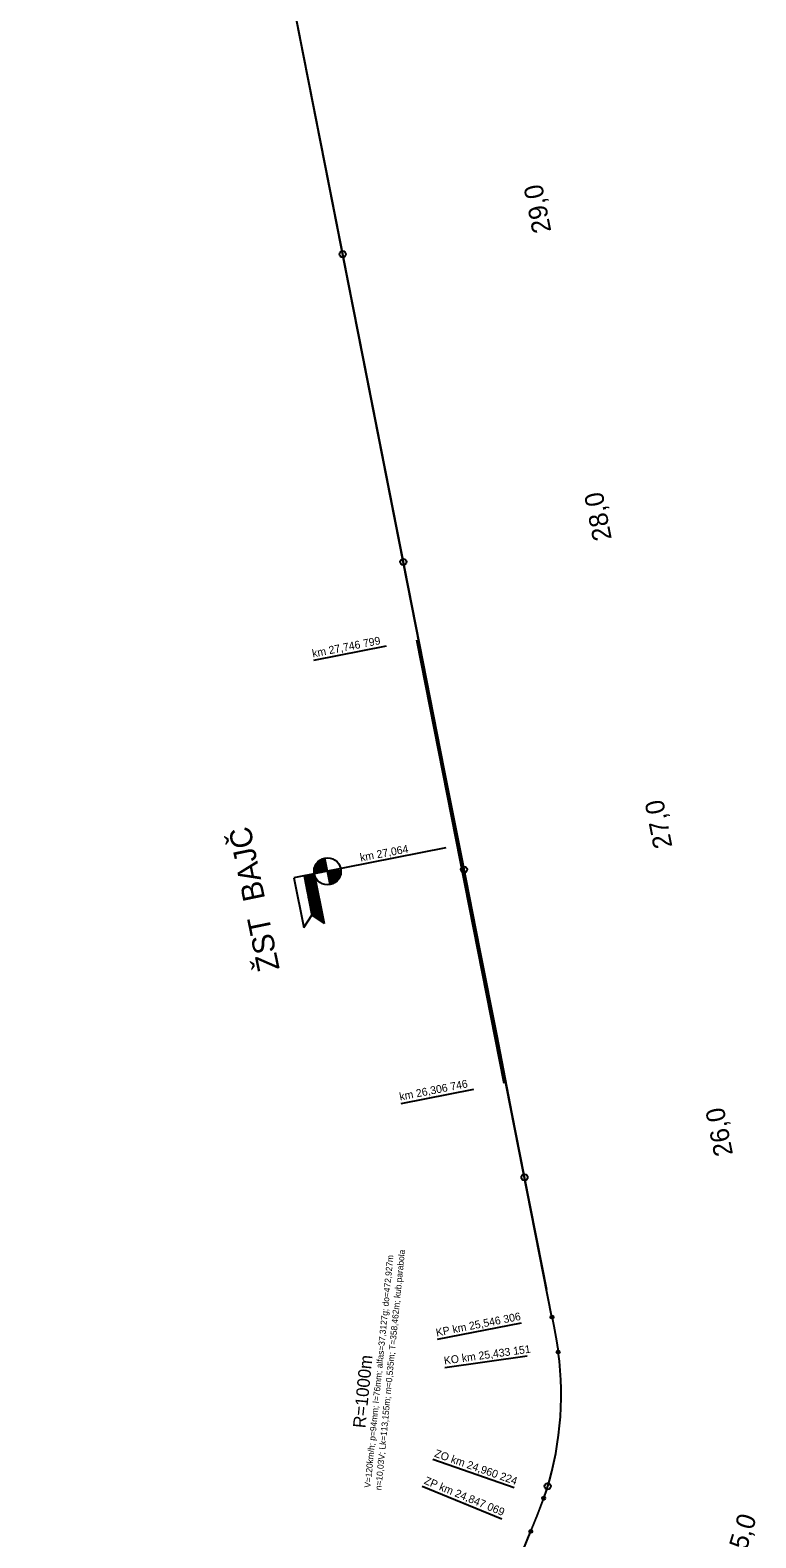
# Model space of a CAD drawing. Extents: x -504999 to -493096, y -1330712 to -1305226.
# Drawn here: x -495411 to -493096, y -1314840 to -1310033 of the extents above; entities that cross this region are included whole.
import ezdxf

# ---------------------------------------------------------------- set-up
doc = ezdxf.new("R2010")
doc.units = 0
for name, color, linetype in [('0_HM', 7, 'Continuous'), ('0_obluky', 7, 'Continuous'), ('0_popis oblukov', 7, 'Continuous'), ('0_STANICE', 7, 'Continuous'), ('0_stanicenie oblukov', 7, 'Continuous'), ('dotyčnice', 7, 'Continuous'), ('Level 1', 7, 'Continuous'), ('PHS', 7, 'Continuous')]:
    doc.layers.add(name, color=color, linetype=linetype)

msp = doc.modelspace()

# ---------------------------------------------------------------- linework, layer by layer
at = {"layer": '0_HM'}
for centre in [(-494413.4, -1310746.9), (-494220.1, -1311728), (-494026.8, -1312709.2), (-493833.6, -1313690.3), (-493759.9, -1314675.3)]:
    msp.add_circle(centre, 10, dxfattribs=at)
at = {"layer": '0_obluky'}
for p, q in [((-493745.9, -1314135.5), (-495397.2, -1305753.2)), ((-494814.6, -1317243.2), (-493813.4, -1314818.5))]:
    msp.add_line(p, q, dxfattribs=at)
for points in [[(-493745.9, -1314135.5), (-493745.7, -1314136.4), (-493745.5, -1314137.4), (-493745.3, -1314138.4), (-493745.1, -1314139.4), (-493744.9, -1314140.4), (-493744.7, -1314141.4), (-493744.5, -1314142.3), (-493744.3, -1314143.3), (-493744.1, -1314144.3), (-493743.9, -1314145.3), (-493743.7, -1314146.3), (-493743.5, -1314147.2), (-493743.4, -1314148.2), (-493743.2, -1314149.2), (-493743, -1314150.2), (-493742.8, -1314151.2), (-493742.6, -1314152.2), (-493742.4, -1314153.1), (-493742.2, -1314154.1), (-493742, -1314155.1), (-493741.8, -1314156.1), (-493741.6, -1314157.1), (-493741.4, -1314158.1), (-493741.2, -1314159), (-493741, -1314160), (-493740.9, -1314161), (-493740.7, -1314162), (-493740.5, -1314163), (-493740.3, -1314164), (-493740.1, -1314164.9), (-493739.9, -1314165.9), (-493739.7, -1314166.9), (-493739.5, -1314167.9), (-493739.3, -1314168.9), (-493739.2, -1314169.8), (-493739, -1314170.8), (-493738.8, -1314171.8), (-493738.6, -1314172.8), (-493738.4, -1314173.8), (-493738.2, -1314174.8), (-493738, -1314175.7), (-493737.8, -1314176.7), (-493737.7, -1314177.7), (-493737.5, -1314178.7), (-493737.3, -1314179.7), (-493737.1, -1314180.7), (-493736.9, -1314181.7), (-493736.7, -1314182.6), (-493736.6, -1314183.6), (-493736.4, -1314184.6), (-493736.2, -1314185.6), (-493736, -1314186.6), (-493735.8, -1314187.6), (-493735.6, -1314188.5), (-493735.5, -1314189.5), (-493735.3, -1314190.5), (-493735.1, -1314191.5), (-493734.9, -1314192.5), (-493734.7, -1314193.5), (-493734.6, -1314194.5), (-493734.4, -1314195.4), (-493734.2, -1314196.4), (-493734, -1314197.4), (-493733.9, -1314198.4), (-493733.7, -1314199.4), (-493733.5, -1314200.4), (-493733.3, -1314201.4), (-493733.2, -1314202.3), (-493733, -1314203.3), (-493732.8, -1314204.3), (-493732.6, -1314205.3), (-493732.5, -1314206.3), (-493732.3, -1314207.3), (-493732.1, -1314208.3), (-493732, -1314209.2), (-493731.8, -1314210.2), (-493731.6, -1314211.2), (-493731.5, -1314212.2), (-493731.3, -1314213.2), (-493731.1, -1314214.2), (-493731, -1314215.2), (-493730.8, -1314216.2), (-493730.6, -1314217.1), (-493730.5, -1314218.1), (-493730.3, -1314219.1), (-493730.1, -1314220.1), (-493730, -1314221.1), (-493729.8, -1314222.1), (-493729.7, -1314223.1), (-493729.5, -1314224.1), (-493729.3, -1314225.1), (-493729.2, -1314226), (-493729, -1314227), (-493728.9, -1314228), (-493728.7, -1314229), (-493728.6, -1314230), (-493728.4, -1314231), (-493728.3, -1314232), (-493728.1, -1314233), (-493728, -1314234), (-493727.8, -1314235), (-493727.7, -1314235.9), (-493727.5, -1314236.9), (-493727.4, -1314237.9), (-493727.2, -1314238.9), (-493727.1, -1314239.9), (-493726.9, -1314240.9), (-493726.8, -1314241.9), (-493726.7, -1314242.9), (-493726.5, -1314243.9), (-493726.4, -1314244.9), (-493726.2, -1314245.9), (-493726.1, -1314246.9)], [(-493813.4, -1314818.5), (-493813, -1314817.6), (-493812.6, -1314816.6), (-493812.2, -1314815.7), (-493811.9, -1314814.8), (-493811.5, -1314813.9), (-493811.1, -1314812.9), (-493810.7, -1314812), (-493810.3, -1314811.1), (-493809.9, -1314810.2), (-493809.6, -1314809.2), (-493809.2, -1314808.3), (-493808.8, -1314807.4), (-493808.4, -1314806.5), (-493808, -1314805.5), (-493807.7, -1314804.6), (-493807.3, -1314803.7), (-493806.9, -1314802.8), (-493806.5, -1314801.8), (-493806.1, -1314800.9), (-493805.8, -1314800), (-493805.4, -1314799.1), (-493805, -1314798.1), (-493804.6, -1314797.2), (-493804.2, -1314796.3), (-493803.9, -1314795.3), (-493803.5, -1314794.4), (-493803.1, -1314793.5), (-493802.7, -1314792.6), (-493802.3, -1314791.6), (-493802, -1314790.7), (-493801.6, -1314789.8), (-493801.2, -1314788.9), (-493800.8, -1314787.9), (-493800.4, -1314787), (-493800.1, -1314786.1), (-493799.7, -1314785.2), (-493799.3, -1314784.2), (-493798.9, -1314783.3), (-493798.6, -1314782.4), (-493798.2, -1314781.4), (-493797.8, -1314780.5), (-493797.4, -1314779.6), (-493797.1, -1314778.7), (-493796.7, -1314777.7), (-493796.3, -1314776.8), (-493795.9, -1314775.9), (-493795.6, -1314774.9), (-493795.2, -1314774), (-493794.8, -1314773.1), (-493794.5, -1314772.2), (-493794.1, -1314771.2), (-493793.7, -1314770.3), (-493793.3, -1314769.4), (-493793, -1314768.4), (-493792.6, -1314767.5), (-493792.2, -1314766.6), (-493791.9, -1314765.6), (-493791.5, -1314764.7), (-493791.1, -1314763.8), (-493790.8, -1314762.9), (-493790.4, -1314761.9), (-493790, -1314761), (-493789.7, -1314760.1), (-493789.3, -1314759.1), (-493788.9, -1314758.2), (-493788.6, -1314757.3), (-493788.2, -1314756.3), (-493787.8, -1314755.4), (-493787.5, -1314754.5), (-493787.1, -1314753.5), (-493786.7, -1314752.6), (-493786.4, -1314751.7), (-493786, -1314750.7), (-493785.7, -1314749.8), (-493785.3, -1314748.9), (-493784.9, -1314747.9), (-493784.6, -1314747), (-493784.2, -1314746.1), (-493783.9, -1314745.1), (-493783.5, -1314744.2), (-493783.2, -1314743.2), (-493782.8, -1314742.3), (-493782.5, -1314741.4), (-493782.1, -1314740.4), (-493781.8, -1314739.5), (-493781.4, -1314738.6), (-493781, -1314737.6), (-493780.7, -1314736.7), (-493780.3, -1314735.7), (-493780, -1314734.8), (-493779.6, -1314733.9), (-493779.3, -1314732.9), (-493779, -1314732), (-493778.6, -1314731), (-493778.3, -1314730.1), (-493777.9, -1314729.2), (-493777.6, -1314728.2), (-493777.2, -1314727.3), (-493776.9, -1314726.3), (-493776.5, -1314725.4), (-493776.2, -1314724.5), (-493775.9, -1314723.5), (-493775.5, -1314722.6), (-493775.2, -1314721.6), (-493774.9, -1314720.7), (-493774.5, -1314719.7), (-493774.2, -1314718.8), (-493773.8, -1314717.8), (-493773.5, -1314716.9), (-493773.2, -1314716), (-493772.8, -1314715), (-493772.5, -1314714.1), (-493772.2, -1314713.1)]]:
    msp.add_lwpolyline(points, dxfattribs=at)
for centre in [(-493745.9, -1314135.5), (-493726.1, -1314246.9), (-493772.2, -1314713.1), (-493813.4, -1314818.5)]:
    msp.add_circle(centre, 5, dxfattribs=at)
msp.add_arc((-494716.6, -1314384.3), 1000, 340.8058, 7.9026, dxfattribs=at)
at = {"layer": '0_STANICE'}
for p, q in [((-494084.9, -1312639.6), (-494569, -1312735.7)), ((-494486, -1312719.2), (-494504.4, -1312707)), ((-494479.1, -1312717.8), (-494503.1, -1312701.8)), ((-494472.2, -1312716.5), (-494501.3, -1312697)), ((-494465.2, -1312715.1), (-494499, -1312692.5)), ((-494462.8, -1312710.7), (-494496.2, -1312688.4)), ((-494464.1, -1312703.8), (-494492.9, -1312684.5)), ((-494465.5, -1312696.9), (-494489.1, -1312681.1)), ((-494466.9, -1312689.9), (-494484.8, -1312677.9)), ((-494468.3, -1312683), (-494479.8, -1312675.3)), ((-494453.6, -1312756.6), (-494470.4, -1312672.2)), ((-494569, -1312735.7), (-494537.7, -1312893.3)), ((-494536.6, -1312729.2), (-494511.7, -1312854.5)), ((-494496.8, -1312760.1), (-494535.6, -1312734.2)), ((-494498.2, -1312753.2), (-494534.6, -1312728.8)), ((-494495.4, -1312767.1), (-494534.2, -1312741.1)), ((-494494, -1312774), (-494532.9, -1312748.1)), ((-494492.7, -1312780.9), (-494531.5, -1312755)), ((-494499.6, -1312746.3), (-494527.7, -1312727.5)), ((-494500.9, -1312739.3), (-494520.7, -1312726.1)), ((-494500.9, -1312739.3), (-494520.7, -1312726.1)), ((-494502.3, -1312732.4), (-494513.8, -1312724.7)), ((-494502.3, -1312732.4), (-494513.8, -1312724.7)), ((-494503.7, -1312725.5), (-494506.9, -1312723.3)), ((-494493, -1312720.6), (-494505, -1312712.6)), ((-494499.9, -1312722), (-494504.8, -1312718.7)), ((-494504.2, -1312722.8), (-494472.9, -1312880.4)), ((-494427.6, -1312740.3), (-494461.4, -1312717.7)), ((-494430.8, -1312744.1), (-494460, -1312724.6)), ((-494434.6, -1312747.6), (-494458.6, -1312731.5)), ((-494424.8, -1312736.1), (-494458.3, -1312713.7)), ((-494438.9, -1312750.7), (-494457.2, -1312738.5)), ((-494443.9, -1312753.4), (-494455.9, -1312745.4)), ((-494449.6, -1312755.6), (-494454.5, -1312752.3)), ((-494422.6, -1312731.6), (-494451.4, -1312712.3)), ((-494420.8, -1312726.8), (-494444.4, -1312711)), ((-494419.6, -1312721.6), (-494437.5, -1312709.6)), ((-494419, -1312715.9), (-494430.6, -1312708.2)), ((-494491.3, -1312787.9), (-494530.1, -1312761.9)), ((-494489.9, -1312794.8), (-494528.7, -1312768.9)), ((-494488.5, -1312801.8), (-494527.4, -1312775.8)), ((-494487.2, -1312808.7), (-494526, -1312782.7)), ((-494485.8, -1312815.6), (-494524.6, -1312789.7)), ((-494484.4, -1312822.6), (-494523.2, -1312796.6)), ((-494483, -1312829.5), (-494521.8, -1312803.5)), ((-494481.7, -1312836.4), (-494520.5, -1312810.5)), ((-494480.3, -1312843.4), (-494519.1, -1312817.4)), ((-494478.9, -1312850.3), (-494517.7, -1312824.4)), ((-494477.5, -1312857.2), (-494516.3, -1312831.3)), ((-494476.1, -1312864.2), (-494515, -1312838.2)), ((-494474.8, -1312871.1), (-494513.6, -1312845.2)), ((-494537.7, -1312893.3), (-494511.7, -1312854.5)), ((-494473.4, -1312878), (-494512.2, -1312852.1)), ((-494511.7, -1312854.5), (-494472.9, -1312880.4))]:
    msp.add_line(p, q, dxfattribs=at)
msp.add_circle((-494462, -1312714.4), 43, dxfattribs=at)
at = {"layer": '0_stanicenie oblukov'}
for p, q in [((-493844, -1314154.8), (-494111.8, -1314207.6)), ((-493825.1, -1314260.6), (-494087.5, -1314297)), ((-493866.6, -1314680.2), (-494126.5, -1314589.8)), ((-493905.8, -1314780.3), (-494159.9, -1314675.4))]:
    msp.add_line(p, q, dxfattribs=at)
at = {"layer": 'dotyčnice'}
msp.add_line((-493763.1, -1314048), (-495410.5, -1305685.7), dxfattribs=at)
at = {"layer": 'Level 1'}
for points in [[(-494844.1, -1308557.6), (-494750.9, -1309033.2), (-494685.7, -1309366.1), (-494664.1, -1309477.1), (-494628, -1309660.7), (-494589.7, -1309856.8), (-494541.4, -1310099.8), (-494450.6, -1310562.1), (-494398.7, -1310826.3), (-494346.7, -1311085.2), (-494265.3, -1311500.4)], [(-494265.3, -1311500.4), (-494180.1, -1311932.6), (-494090.4, -1312387.7), (-494032.7, -1312680.3), (-493977.2, -1312961.9), (-493922.3, -1313239.3), (-493873.8, -1313487.4), (-493835.8, -1313681.7), (-493777.1, -1313977.6), (-493763.1, -1314048)]]:
    msp.add_lwpolyline(points, dxfattribs=at)
at = {"layer": 'PHS'}
for p, q in [((-493898.7, -1313390.5), (-494177.1, -1311977.6)), ((-494275.2, -1311997), (-494506.4, -1312042.5)), ((-493996.8, -1313409.9), (-494228.1, -1313455.4))]:
    msp.add_line(p, q, dxfattribs=at)

# ---------------------------------------------------------------- texts
at = {"layer": '0_HM'}
for s, rotation, p in [('29,0', 101.1449, (-493747.9, -1310673.6)), ('28,0', 101.1449, (-493554.9, -1311654.5)), ('27,0', 101.1449, (-493361.6, -1312635.6)), ('26,0', 101.1449, (-493168.3, -1313616.8)), ('25,0', 73.0848, (-493138.1, -1314923.7))]:
    msp.add_text(s, height=60, rotation=rotation, dxfattribs=at).set_placement(p)
at = {"layer": '0_popis oblukov'}
for s, height, p in [('V=120km/h; p=94mm; I=76mm; alfas=37,3127g; do=472,927m', 20, (-494324.8, -1314680.8)), ('n=10,03V; Lk=113,155m; m=0,535m; T=358,462m; kub.parabola', 20, (-494290.4, -1314688.4)), ('R=1000m', 40, (-494341.2, -1314490.9))]:
    msp.add_text(s, height=height, rotation=84.3542, dxfattribs=at).set_placement(p)
at = {"layer": '0_STANICE'}
for s, height, rotation, p in [('ŽST  BAJČ', 70, 101.6791, (-494614.3, -1313025.9)), (' km 27,064', 25, 10.5404, (-494365, -1312684.7))]:
    msp.add_text(s, height=height, rotation=rotation, dxfattribs=at).set_placement(p)
at = {"layer": '0_stanicenie oblukov'}
for s, rotation, p in [('KP km 25,546 306', 11.1449, (-494113.7, -1314197.7)), ('KO km 25,433 151', 7.9026, (-494088.9, -1314287.1)), ('ZO km 24,960 224', 340.8058, (-494123.2, -1314580.3)), ('ZP km 24,847 069', 337.5635, (-494156.1, -1314666.2))]:
    msp.add_text(s, height=25, rotation=rotation, dxfattribs=at).set_placement(p)
at = {"layer": 'PHS'}
for s, p in [('km 27,746 799', (-494508.4, -1312032.7)), ('km 26,306 746', (-494230, -1313445.6))]:
    msp.add_text(s, height=25, rotation=11.1449, dxfattribs=at).set_placement(p)

doc.saveas('drawing.dxf')
